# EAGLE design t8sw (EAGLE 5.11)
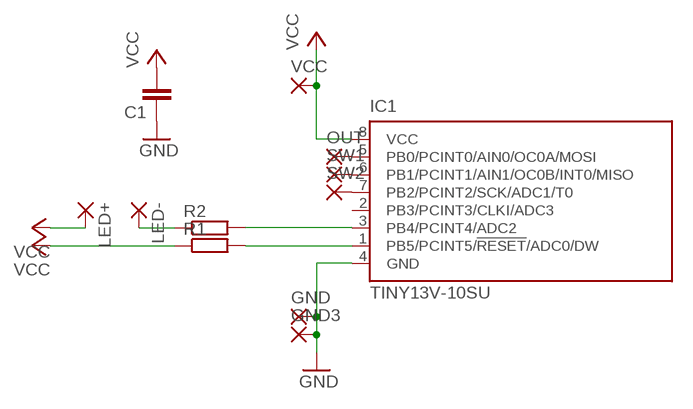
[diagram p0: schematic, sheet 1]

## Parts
C1  C-EUC0402  [C0402]
GND  SMD5  [SMD2,54-5,08]
GND3  SMD5  [SMD2,54-5,08]
IC1  TINY13V-10SU  [8S2]
LED+  SMD5  [SMD2,54-5,08]
LED-  SMD5  [SMD2,54-5,08]
OUT  SMD5  [SMD2,54-5,08]
R1  R-EU_R0402  [R0402]
R2  R-EU_R0402  [R0402]
SW1  SMD5  [SMD2,54-5,08]
SW2  SMD5  [SMD2,54-5,08]
VCC  SMD5  [SMD2,54-5,08]

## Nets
GND: C1.1 GND3.1(P) GND.1(P) IC1.4(GND)
N$1: IC1.5(PB0/PCINT0/AIN0/OC0A/MOSI) OUT.1(P)
N$2: IC1.6(PB1/PCINT1/AIN1/OC0B/INT0/MISO) SW1.1(P)
N$3: IC1.1(PB5/PCINT5/!RESET!/ADC0/DW) R1.2
N$4: IC1.3(PB4/PCINT4/ADC2) R2.2
N$5: LED-.1(P) R2.1
N$6: IC1.7(PB2/PCINT2/SCK/ADC1/T0) SW2.1(P)
VCC: C1.2 IC1.8(VCC) LED+.1(P) R1.1 VCC.1(P)
Unconnected: IC1.2(PB3/PCINT3/CLKI/ADC3)

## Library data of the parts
C1 = rcl:C-EU: CAPACITOR, European symbol
GND GND3 LED+ LED- OUT SW1 SW2 VCC = wirepad:SMD5: SMD PAD
IC1 = atmel:TINY13: 8-bit AVR Microcontroller with 1K Bytes In-System Programmable Flash Source: http://www.atmel.com/dyn/resources/prod_documents/2535S.pdf; MPN: ATTINY13V-10SU; OC_FARNELL: 9171584; OC_NEWARK: 96K6524
R1 R2 = rcl:R-EU_: RESISTOR, European symbol

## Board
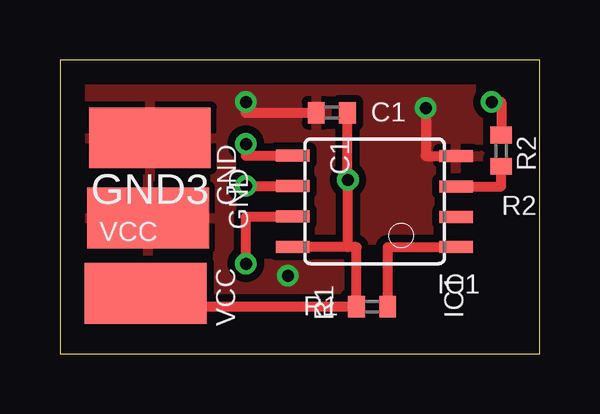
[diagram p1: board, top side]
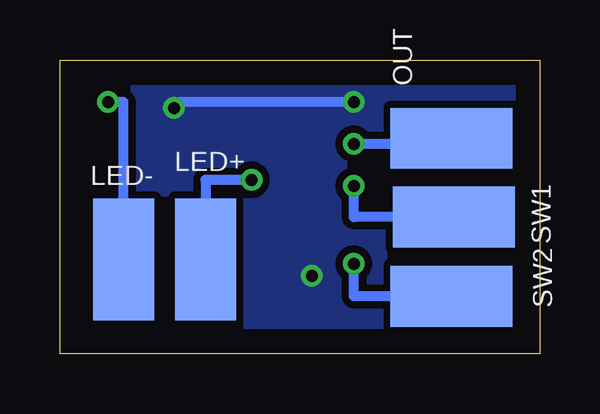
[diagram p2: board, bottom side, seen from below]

Size 20 x 12.25 mm. Coordinates in mm from the lower left corner, seen from the top.
Outline: 0,0 20,0 20,12.25 0,12.25 0,0
Copper layers (1*16): Top 0.035mm / dielectric 1.5mm / Bottom 0.035mm
Design rules "default *": minimum track width 10mil, minimum drill 24mil, track to track 8mil, track to pad 8mil, pad to pad 8mil, via to via 8mil, smd to smd 8mil, copper to edge 40mil, drill to drill 8mil, minimum pad ring 10mil, minimum via ring 8mil, stop-mask expansion 4mil, vias tented up to drill 30mil, thermal gap 10mil

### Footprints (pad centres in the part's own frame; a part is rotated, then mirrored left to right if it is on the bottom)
C0402 = smd 0.7 x 0.9: 1 -0.65,0; 2 0.65,0
SMD2,54-5,08 = smd 2.54 x 5.08: 1 0,0
8S2 = smd 0.5 x 1.4: 1 -1.905,-3.404; 2 -0.645,-3.404; 3 0.625,-3.404; 4 1.895,-3.404; 5 1.905,3.404; 6 0.635,3.404; 7 -0.635,3.404; 8 -1.905,3.404
R0402 = smd 0.7 x 0.9: 1 -0.65,0; 2 0.65,0

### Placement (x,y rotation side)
C1  11.34,10.05 0 top
GND  3.67,5.66 270 top
GND3  3.75,9 90 top
IC1  13.11,6.35 90 top
LED+  13.93,3.92 0 bottom
LED-  17.35,3.92 0 bottom
OUT  3.67,8.98 270 bottom
R1  13.02,1.96 0 top
R2  18.4,8.46 270 top
SW1  3.58,5.69 90 bottom
SW2  3.67,2.39 270 bottom
VCC  3.58,2.51 90 top

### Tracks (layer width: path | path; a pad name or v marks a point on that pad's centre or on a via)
GND  (via drill 0.5)
  Top 0.406: IC1.4 15.25,8.24 v15.25,10.25 | C1.1 7.75,10.05 v7.75,10.5
  Bottom 0.406: v15.25,10.25 15.25,10.5 v7.75,10.5
  other vias: 9.5,3.25
  pour Top (isolate 0.305): 0,0 20,0 20,12.25 0,12.25
  pour Bottom (isolate 0.305): 0,0 20,0 20,12.25 0,12.25
N$1  (via drill 0.5)
  Top 0.406: IC1.5 7.75,8.26 v7.75,8.75
  Bottom 0.406: v7.75,8.75 3.67,8.75 OUT.1
N$2  (via drill 0.5)
  Top 0.406: IC1.6 9.71,7 v7.75,7
  Bottom 0.406: v7.75,7 7.75,5.69 SW1.1
N$3
  Top 0.406: R1.2 13.67,4.45 IC1.1
N$4
  Top 0.406: IC1.3 18.4,6.97 R2.2
N$5  (via drill 0.5)
  Top 0.406: v18,10.5 18.4,10.5 R2.1
  Bottom 0.406: LED-.1 17.35,10.5 v18,10.5
N$6  (via drill 0.5)
  Top 0.406: IC1.7 7.75,5.71 v7.75,3.75
  Bottom 0.406: v7.75,3.75 7.75,2.39 SW2.1
VCC  (via drill 0.5)
  Top 0.406: 12.01,4.45 IC1.8 | 12.01,4.45 12.37,4.45 R1.1 3.58,1.96 VCC.1 | 12.01,4.45 v12.01,7.25 11.99,7.25 C1.2
  Bottom 0.406: LED+.1 13.93,7.25 v12.01,7.25

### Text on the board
bStop: LED- | OUT | LED+ | SW1 | SW2
_tNames: C1 | GND | R2 | VCC | IC1 | R1
_tValues: TINY13V-10SU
